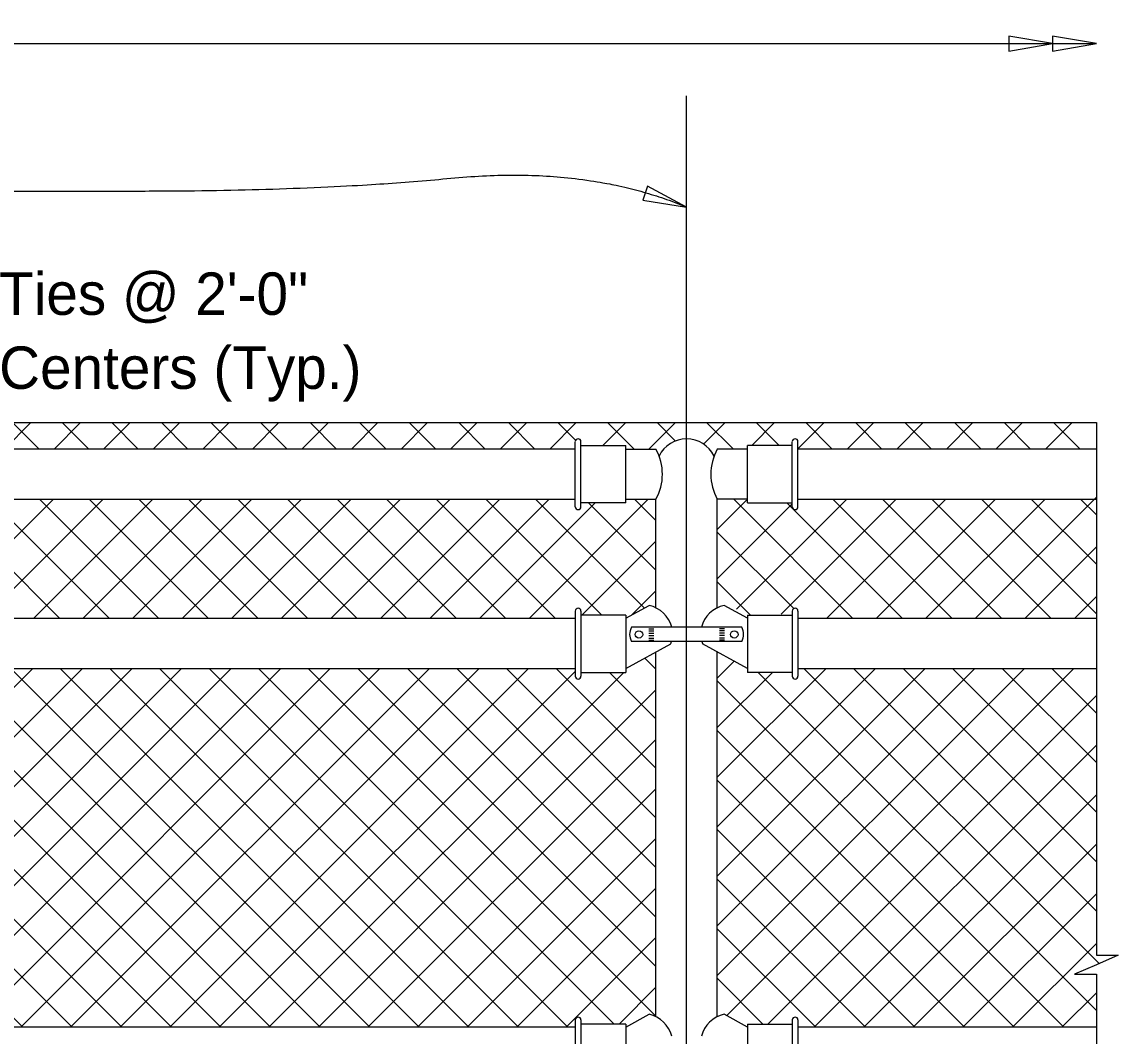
# Model space of a CAD drawing. Extents: x 110341.7 to 110413.5, y 110387.3 to 110417.8.
# Drawn here: x 110362.42 to 110367.63, y 110410.5 to 110415.33 of the extents above; entities that cross this region are included whole.
import ezdxf

# ---------------------------------------------------------------- set-up
doc = ezdxf.new("R2010")
doc.units = 0
for name, color, linetype in [('AdhocPoint_dp', 7, 'Continuous'), ('Border', 7, 'Continuous'), ('CL_Major', 7, 'Continuous'), ('Patterning', 7, 'Continuous')]:
    doc.layers.add(name, color=color, linetype=linetype)

msp = doc.modelspace()

# ---------------------------------------------------------------- linework, layer by layer
at = {"layer": 'AdhocPoint_dp'}
for p, q in [((110365.0484, 110413.022), (110365.0484, 110413.3316)), ((110365.0753, 110413.022), (110365.0753, 110413.3316)), ((110366.0803, 110413.022), (110366.0803, 110413.3316)), ((110366.1071, 110413.022), (110366.1071, 110413.3316)), ((110365.0484, 110413.2966), (110361.1164, 110413.2966)), ((110365.0753, 110413.3138), (110365.2882, 110413.3138)), ((110365.2882, 110413.0415), (110365.2882, 110413.3138)), ((110365.2882, 110413.2957), (110365.4319, 110413.2957)), ((110365.8674, 110413.2957), (110365.7237, 110413.2957)), ((110365.8673, 110413.0415), (110365.8673, 110413.3138)), ((110366.0803, 110413.3138), (110365.8673, 110413.3138)), ((110367.5259, 110413.2966), (110366.1071, 110413.2966)), ((110365.0484, 110413.057), (110361.1164, 110413.057)), ((110365.2882, 110413.0415), (110365.0753, 110413.0415)), ((110365.2882, 110413.058), (110365.4319, 110413.058)), ((110365.432, 110412.5414), (110365.432, 110413.058)), ((110365.7237, 110412.5414), (110365.7237, 110413.058)), ((110365.8674, 110413.058), (110365.7237, 110413.058)), ((110365.8673, 110413.0415), (110366.0803, 110413.0415)), ((110367.5259, 110413.057), (110366.1071, 110413.057)), ((110365.2882, 110412.4919), (110365.3991, 110412.5532)), ((110365.8673, 110412.4919), (110365.7565, 110412.5532)), ((110365.0484, 110412.4912), (110361.1164, 110412.4912)), ((110365.0484, 110412.5261), (110365.0484, 110412.2165)), ((110365.0753, 110412.5261), (110365.0753, 110412.2165)), ((110365.2882, 110412.5066), (110365.0753, 110412.5066)), ((110365.2882, 110412.5066), (110365.2882, 110412.2344)), ((110365.8673, 110412.5066), (110365.8673, 110412.2344)), ((110365.8673, 110412.5066), (110366.0803, 110412.5066)), ((110366.0803, 110412.5261), (110366.0803, 110412.2165)), ((110366.1071, 110412.5261), (110366.1071, 110412.2165)), ((110367.5259, 110412.4912), (110366.1071, 110412.4912)), ((110365.8402, 110412.4493), (110365.3154, 110412.4493)), ((110365.3978, 110412.4415), (110365.4212, 110412.4415)), ((110365.7578, 110412.4415), (110365.7343, 110412.4415)), ((110365.3978, 110412.4319), (110365.4212, 110412.4319)), ((110365.3978, 110412.421), (110365.4212, 110412.421)), ((110365.3978, 110412.4093), (110365.4212, 110412.4093)), ((110365.3978, 110412.3975), (110365.4212, 110412.3975)), ((110365.3978, 110412.3877), (110365.4212, 110412.3877)), ((110365.7578, 110412.4319), (110365.7343, 110412.4319)), ((110365.7578, 110412.421), (110365.7343, 110412.421)), ((110365.7578, 110412.4093), (110365.7343, 110412.4093)), ((110365.7578, 110412.3975), (110365.7343, 110412.3975)), ((110365.7578, 110412.3877), (110365.7343, 110412.3877)), ((110365.2882, 110412.2525), (110365.5022, 110412.371)), ((110365.8402, 110412.3815), (110365.3154, 110412.3815)), ((110365.432, 110410.5968), (110365.432, 110412.3322)), ((110365.8673, 110412.2525), (110365.6534, 110412.371)), ((110365.7237, 110410.5969), (110365.7237, 110412.3321)), ((110365.0484, 110412.2516), (110361.1164, 110412.2516)), ((110365.0753, 110412.2344), (110365.2882, 110412.2344)), ((110366.0803, 110412.2344), (110365.8673, 110412.2344)), ((110367.5259, 110412.2516), (110366.1071, 110412.2516)), ((110365.0484, 110410.5816), (110365.0484, 110410.272)), ((110365.0753, 110410.5816), (110365.0753, 110410.272)), ((110365.2882, 110410.5621), (110365.0753, 110410.5621)), ((110365.2882, 110410.5473), (110365.3991, 110410.6087)), ((110365.2882, 110410.5621), (110365.2882, 110410.2898)), ((110365.8673, 110410.5473), (110365.7565, 110410.6087)), ((110365.8673, 110410.5621), (110365.8673, 110410.2898)), ((110365.8673, 110410.5621), (110366.0803, 110410.5621)), ((110366.0803, 110410.5816), (110366.0803, 110410.272)), ((110366.1071, 110410.5816), (110366.1071, 110410.272)), ((110365.0484, 110410.5466), (110361.1164, 110410.5466)), ((110367.5259, 110410.5466), (110366.1071, 110410.5466))]:
    msp.add_line(p, q, dxfattribs=at)
for centre, radius, start, end in [((110365.062, 110413.332), 0.0134, 0, 180), ((110365.5778, 110413.1987), 0.1459, 26.2495, 153.7505), ((110366.0936, 110413.332), 0.0134, 0, 180), ((110365.2183, 110413.1768), 0.2445, 330.9208, 29.0792), ((110365.9373, 110413.1768), 0.2445, 150.9208, 209.0792), ((110365.062, 110413.0222), 0.0134, 180, 0), ((110366.0936, 110413.0222), 0.0134, 180, 0), ((110365.062, 110412.5261), 0.0134, 0, 180), ((110366.0936, 110412.5261), 0.0134, 0, 180), ((110365.062, 110412.2163), 0.0134, 180, 0), ((110366.0936, 110412.2163), 0.0134, 180, 0), ((110365.062, 110410.5815), 0.0134, 0, 180), ((110366.0936, 110410.5815), 0.0134, 0, 180)]:
    msp.add_arc(centre, radius, start, end, dxfattribs=at)
for centre, major_axis, start_param, end_param in [((110365.3646, 110412.4173), (0.146, 0), 0.231126, 1.331255), ((110365.791, 110412.4173), (-0.146, 0), 4.95193, 6.05206), ((110365.3846, 110412.4153), (-0.0776, 0), 5.810211, 6.75616), ((110365.771, 110412.4153), (0.0776, 0), 5.810211, 6.75616), ((110365.3646, 110412.4173), (0.146, 0), 5.947976, 6.024627), ((110365.791, 110412.4173), (-0.146, 0), 0.258558, 0.335209), ((110365.3646, 110410.4727), (0.146, 0), 0.231126, 1.331255), ((110365.791, 110410.4727), (-0.146, 0), 4.95193, 6.05206)]:
    msp.add_ellipse(centre, major_axis=major_axis, ratio=0.957868, start_param=start_param, end_param=end_param, dxfattribs=at)
for centre, major_axis in [((110365.3512, 110412.4148), (0.0178, 0)), ((110365.8044, 110412.4148), (-0.0178, 0))]:
    msp.add_ellipse(centre, major_axis=major_axis, ratio=0.957868, dxfattribs=at)
at = {"layer": 'Border'}
for points in [[(110354.5778, 110415.2246), (110356.0414, 110415.2246), (110356.0414, 110415.3279), (110356.0864, 110415.2246), (110356.1314, 110415.1213), (110356.1314, 110415.2246), (110367.5259, 110415.2246)], [(110367.5259, 110413.4227), (110367.5259, 110410.8892), (110367.6293, 110410.8892), (110367.5259, 110410.8442), (110367.4226, 110410.7992), (110367.5259, 110410.7992), (110367.5259, 110410.307)]]:
    msp.add_lwpolyline(points, dxfattribs=at)
for points in [[(110367.3177, 110415.2246), (110367.1094, 110415.2599), (110367.1094, 110415.1893)], [(110367.5259, 110415.2246), (110367.3177, 110415.2599), (110367.3177, 110415.1893)], [(110365.5778, 110414.4473), (110365.3914, 110414.5467), (110365.3691, 110414.4798)]]:
    msp.add_lwpolyline(points, close=True, dxfattribs=at)
msp.add_open_spline([(110361.6532, 110414.5236), (110362.0656, 110414.5236), (110363.8331, 110414.5236), (110365.0996, 110414.6466), (110365.5778, 110414.4473)], degree=2, dxfattribs=at)
at = {"layer": 'CL_Major'}
msp.add_line((110365.5778, 110401.2111), (110365.5778, 110414.9771), dxfattribs=at)
at = {"layer": 'Patterning'}
for p, q in [((110361.6525, 110413.4227), (110367.526, 110413.4227)), ((110362.3345, 110413.2966), (110362.4605, 110413.4227)), ((110362.3733, 110413.4227), (110362.4993, 110413.2966)), ((110362.5702, 110413.2966), (110362.6962, 110413.4227)), ((110362.609, 110413.4227), (110362.735, 110413.2966)), ((110362.8059, 110413.2966), (110362.9319, 110413.4227)), ((110362.8447, 110413.4227), (110362.9707, 110413.2966)), ((110363.0416, 110413.2966), (110363.1676, 110413.4227)), ((110363.0804, 110413.4227), (110363.2064, 110413.2966)), ((110363.2773, 110413.2966), (110363.4033, 110413.4227)), ((110363.3161, 110413.4227), (110363.4421, 110413.2966)), ((110363.513, 110413.2966), (110363.639, 110413.4227)), ((110363.5518, 110413.4227), (110363.6778, 110413.2966)), ((110363.7487, 110413.2966), (110363.8747, 110413.4227)), ((110363.7875, 110413.4227), (110363.9135, 110413.2966)), ((110363.9844, 110413.2966), (110364.1104, 110413.4227)), ((110364.0232, 110413.4227), (110364.1492, 110413.2966)), ((110364.2201, 110413.2966), (110364.3461, 110413.4227)), ((110364.2589, 110413.4227), (110364.3849, 110413.2966)), ((110364.4558, 110413.2966), (110364.5818, 110413.4227)), ((110364.4946, 110413.4227), (110364.6206, 110413.2966)), ((110364.6915, 110413.2966), (110364.8175, 110413.4227)), ((110364.7303, 110413.4227), (110364.8563, 110413.2966)), ((110364.9272, 110413.2966), (110365.0532, 110413.4227)), ((110364.966, 110413.4227), (110365.0502, 110413.3385)), ((110365.18, 110413.3138), (110365.2889, 110413.4227)), ((110365.2017, 110413.4227), (110365.3287, 110413.2957)), ((110365.3976, 110413.2957), (110365.5246, 110413.4227)), ((110365.4374, 110413.4227), (110365.5253, 110413.3348)), ((110365.6579, 110413.3203), (110365.7603, 110413.4227)), ((110365.6731, 110413.4227), (110365.8001, 110413.2957)), ((110365.8871, 110413.3138), (110365.996, 110413.4227)), ((110365.9088, 110413.4227), (110366.0177, 110413.3138)), ((110366.1071, 110413.2981), (110366.2317, 110413.4227)), ((110366.1445, 110413.4227), (110366.2705, 110413.2966)), ((110366.3414, 110413.2966), (110366.4674, 110413.4227)), ((110366.3802, 110413.4227), (110366.5062, 110413.2966)), ((110366.5771, 110413.2966), (110366.7031, 110413.4227)), ((110366.6159, 110413.4227), (110366.7419, 110413.2966)), ((110366.8128, 110413.2966), (110366.9388, 110413.4227)), ((110366.8516, 110413.4227), (110366.9776, 110413.2966)), ((110367.0485, 110413.2966), (110367.1745, 110413.4227)), ((110367.0873, 110413.4227), (110367.2133, 110413.2966)), ((110367.2842, 110413.2966), (110367.4103, 110413.4227)), ((110367.323, 110413.4227), (110367.4491, 110413.2966)), ((110366.9501, 110412.4912), (110367.526, 110413.067)), ((110362.0004, 110412.4912), (110362.5663, 110413.057)), ((110362.0318, 110413.057), (110362.5977, 110412.4912)), ((110362.2361, 110412.4912), (110362.802, 110413.057)), ((110362.2675, 110413.057), (110362.8334, 110412.4912)), ((110362.4718, 110412.4912), (110363.0377, 110413.057)), ((110362.5032, 110413.057), (110363.0691, 110412.4912)), ((110362.7075, 110412.4912), (110363.2734, 110413.057)), ((110362.7389, 110413.057), (110363.3048, 110412.4912)), ((110362.9432, 110412.4912), (110363.5091, 110413.057)), ((110362.9746, 110413.057), (110363.5405, 110412.4912)), ((110363.1789, 110412.4912), (110363.7448, 110413.057)), ((110363.2103, 110413.057), (110363.7762, 110412.4912)), ((110363.4146, 110412.4912), (110363.9805, 110413.057)), ((110363.446, 110413.057), (110364.0119, 110412.4912)), ((110363.6503, 110412.4912), (110364.2162, 110413.057)), ((110363.6817, 110413.057), (110364.2476, 110412.4912)), ((110363.886, 110412.4912), (110364.4519, 110413.057)), ((110363.9174, 110413.057), (110364.4833, 110412.4912)), ((110364.1217, 110412.4912), (110364.6876, 110413.057)), ((110364.1531, 110413.057), (110364.719, 110412.4912)), ((110364.3574, 110412.4912), (110364.9233, 110413.057)), ((110364.3888, 110413.057), (110364.9547, 110412.4912)), ((110364.5931, 110412.4912), (110365.1435, 110413.0415)), ((110364.6245, 110413.057), (110365.1749, 110412.5066)), ((110364.8288, 110412.4912), (110365.3957, 110413.058)), ((110364.8602, 110413.057), (110365.3765, 110412.5408)), ((110365.1114, 110413.0415), (110365.432, 110412.721)), ((110365.3307, 110413.058), (110365.432, 110412.9567)), ((110365.7237, 110412.9146), (110365.8628, 110413.0538)), ((110365.7237, 110412.6789), (110366.0803, 110413.0356)), ((110365.8021, 110413.058), (110366.3689, 110412.4912)), ((110365.8153, 110412.5348), (110366.3375, 110413.057)), ((110366.0275, 110412.5113), (110366.5732, 110413.057)), ((110366.0542, 110413.0415), (110366.6046, 110412.4912)), ((110366.243, 110412.4912), (110366.8089, 110413.057)), ((110366.2744, 110413.057), (110366.8403, 110412.4912)), ((110366.4787, 110412.4912), (110367.0446, 110413.057)), ((110366.5101, 110413.057), (110367.076, 110412.4912)), ((110366.7144, 110412.4912), (110367.2803, 110413.057)), ((110366.7458, 110413.057), (110367.3117, 110412.4912)), ((110366.9815, 110413.057), (110367.526, 110412.5126)), ((110367.2172, 110413.057), (110367.526, 110412.7483)), ((110367.4529, 110413.057), (110367.526, 110412.984)), ((110365.08, 110412.5066), (110365.432, 110412.8586)), ((110365.7237, 110412.9007), (110366.0868, 110412.5376)), ((110367.1859, 110412.4912), (110367.526, 110412.8313)), ((110365.7237, 110412.665), (110365.882, 110412.5066)), ((110365.3167, 110412.5077), (110365.432, 110412.6229)), ((110367.4216, 110412.4912), (110367.526, 110412.5956)), ((110365.3788, 110412.3027), (110365.432, 110412.2496)), ((110365.7237, 110412.2075), (110365.8039, 110412.2877)), ((110360.7159, 110412.2516), (110362.4209, 110410.5466)), ((110360.8848, 110410.6685), (110362.4679, 110412.2516)), ((110360.9516, 110412.2516), (110362.6566, 110410.5466)), ((110360.9914, 110410.5393), (110362.7036, 110412.2516)), ((110361.1873, 110412.2516), (110362.8923, 110410.5466)), ((110361.2344, 110410.5466), (110362.9393, 110412.2516)), ((110361.423, 110412.2516), (110363.128, 110410.5466)), ((110361.4701, 110410.5466), (110363.175, 110412.2516)), ((110361.6587, 110412.2516), (110363.3637, 110410.5466)), ((110361.7058, 110410.5466), (110363.4107, 110412.2516)), ((110361.8944, 110412.2516), (110363.5994, 110410.5466)), ((110361.9415, 110410.5466), (110363.6464, 110412.2516)), ((110362.1301, 110412.2516), (110363.8351, 110410.5466)), ((110362.1772, 110410.5466), (110363.8821, 110412.2516)), ((110362.3658, 110412.2516), (110364.0708, 110410.5466)), ((110362.4129, 110410.5466), (110364.1178, 110412.2516)), ((110362.6015, 110412.2516), (110364.3065, 110410.5466)), ((110362.6486, 110410.5466), (110364.3535, 110412.2516)), ((110362.8372, 110412.2516), (110364.5422, 110410.5466)), ((110362.8843, 110410.5466), (110364.5892, 110412.2516)), ((110363.0729, 110412.2516), (110364.7779, 110410.5466)), ((110363.12, 110410.5466), (110364.8249, 110412.2516)), ((110363.3086, 110412.2516), (110365.0136, 110410.5466)), ((110363.3557, 110410.5466), (110365.0484, 110412.2394)), ((110363.5443, 110412.2516), (110365.2338, 110410.5621)), ((110363.5914, 110410.5466), (110365.2792, 110412.2344)), ((110363.78, 110412.2516), (110365.432, 110410.5996)), ((110364.0157, 110412.2516), (110365.432, 110410.8353)), ((110364.2515, 110412.2516), (110365.432, 110411.071)), ((110364.4872, 110412.2516), (110365.432, 110411.3067)), ((110364.7229, 110412.2516), (110365.432, 110411.5424)), ((110364.9586, 110412.2516), (110365.432, 110411.7782)), ((110365.2114, 110412.2344), (110365.432, 110412.0139)), ((110365.7237, 110410.7933), (110367.182, 110412.2516)), ((110365.7237, 110411.029), (110366.9463, 110412.2516)), ((110365.7237, 110411.2647), (110366.7106, 110412.2516)), ((110365.7237, 110411.5004), (110366.4749, 110412.2516)), ((110365.7237, 110411.7361), (110366.2392, 110412.2516)), ((110365.7237, 110411.9718), (110365.9863, 110412.2344)), ((110365.7683, 110410.6022), (110367.4177, 110412.2516)), ((110365.9186, 110412.2344), (110367.526, 110410.627)), ((110366.1371, 110412.2516), (110367.5388, 110410.8498)), ((110366.3728, 110412.2516), (110367.526, 110411.0984)), ((110366.6085, 110412.2516), (110367.526, 110411.3341)), ((110366.8442, 110412.2516), (110367.526, 110411.5698)), ((110367.0799, 110412.2516), (110367.526, 110411.8055)), ((110367.3156, 110412.2516), (110367.526, 110412.0412)), ((110365.7237, 110412.1936), (110367.3706, 110410.5466)), ((110363.8271, 110410.5466), (110365.432, 110412.1515)), ((110365.9639, 110410.5621), (110367.526, 110412.1242)), ((110364.0628, 110410.5466), (110365.432, 110411.9158)), ((110365.7237, 110411.9579), (110367.1349, 110410.5466)), ((110366.1841, 110410.5466), (110367.526, 110411.8885)), ((110365.7237, 110411.7222), (110366.8992, 110410.5466)), ((110364.2985, 110410.5466), (110365.432, 110411.6801)), ((110366.4198, 110410.5466), (110367.526, 110411.6528)), ((110365.7237, 110411.4865), (110366.6635, 110410.5466)), ((110364.5342, 110410.5466), (110365.432, 110411.4444)), ((110366.6555, 110410.5466), (110367.526, 110411.4171)), ((110365.7237, 110411.2508), (110366.4278, 110410.5466)), ((110364.7699, 110410.5466), (110365.432, 110411.2087)), ((110366.8912, 110410.5466), (110367.526, 110411.1814)), ((110365.7237, 110411.0151), (110366.1921, 110410.5466)), ((110365.0056, 110410.5466), (110365.432, 110410.973)), ((110367.1269, 110410.5466), (110367.526, 110410.9457)), ((110365.7237, 110410.7794), (110365.9409, 110410.5621)), ((110365.2568, 110410.5621), (110365.432, 110410.7373)), ((110367.3626, 110410.5466), (110367.526, 110410.71))]:
    msp.add_line(p, q, dxfattribs=at)

# ---------------------------------------------------------------- texts
at = {"layer": 'Border'}
for s, p in [('Ties @ 2\'-0" ', (110362.3089, 110413.9348)), ('Centers (Typ.)', (110362.3089, 110413.5828))]:
    msp.add_text(s, height=0.2016, dxfattribs=at).set_placement(p)

doc.saveas('drawing.dxf')
